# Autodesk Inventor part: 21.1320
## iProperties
Created: 2006-12
Part Number: 21.1320
Document SubType Name: Modeling
Designer: Andy Moles
Material: Steel, Mild
Density: 7.86 g/cm^3
Mass: 5.31606 g
Surface Area: 5.644 cm^2
Volume: 0.676344 cm^3
Author: Andy Moles
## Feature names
1. Extrusion1
2. Revolution1
